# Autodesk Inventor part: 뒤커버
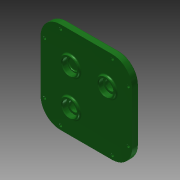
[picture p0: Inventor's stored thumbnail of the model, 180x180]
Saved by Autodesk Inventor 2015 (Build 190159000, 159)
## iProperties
Created: 2016-12
Part Number: 뒤커버
Material: 알루미늄 6061
Document SubType Name: Modeling
Designer: mduedu
Density: 2.71 g/cm^3
Appearance: 매끄러움 - 짙은 산림 녹색
Mass: 485.372 g
Surface Area: 454.562 cm^2
Volume: 179.104 cm^3
Author: mduedu
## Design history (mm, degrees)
sketch "스케치1"
  geometry: L1 (-46, 42)-(-46, -36); L2 (-16, 72)-(62, 72); L3 (92, 42)-(92, -36); L4 (62, -66)-(-16, -66); A1 r 30 centre (-16, -36) between (-46, -36) and (-16, -66); A2 r 30 centre (62, 42) between (92, 42) and (62, 72); A3 r 30 centre (62, -36) between (62, -66) and (92, -36); A4 r 30 centre (-16, 42) between (-16, 72) and (-46, 42); 1 further point
  constraints: 8 end point, 8 point on circle, 8 tangent, 4 centre point, 3 equal radius, 2 perpendicular, 1 horizontal, 1 vertical
  dimensions: "d80" = 30 radius of A2; "d81" = 138 distance between parallel lines of L4 L2; "d82" = 92 distance from line of L3 point (0, 0); "d114" = 46 distance from line of L1 point (0, 0); "d115" = 72 distance from line of L2 point (0, 0)
extrude "돌출1" new body sketch "스케치1" distance "d3" = 10; taper "d4" = 0 deg
sketch "스케치2"
  geometry: C1 r 14 at (0, 26); 1 further point
  constraints: 1 centre point, 1 vertical alignment
  dimensions: "d5" = 28 diameter of C1; "d6" = 26 distance of C1.centre point (0, 0)
extrude "돌출2" join sketch "스케치2" distance "d7" = 3; taper "d8" = 0 deg
sketch "스케치3"
  geometry: C1 r 14 at (0, -28.87); C2 r 14 at (0, 26) reference; C3 r 14 at (54.87, 26); 1 further point
  constraints: 2 centre point, 1 horizontal alignment, 1 vertical alignment
  dimensions: "d9" = 28 diameter of C1; "d69" = 54.87 distance of C1.centre C2.centre; "d83" = 28 diameter of C3; "d84" = 54.87 distance of C3.centre C2.centre
extrude "돌출3" join sketch "스케치3" distance "d11" = 3; taper "d12" = 0 deg
hole "구멍1" diameter "d15" = 22; stored, may be unused: countersink angle "d19" = 90 deg, drill point angle "d21" = 0 deg; dims "d13" = 10, "d14" = 10, "d16" = 6, "d17" = 4, "d18" = 2, "d20" = 7
hole "구멍2" diameter "d24" = 18; stored, may be unused: countersink angle "d28" = 90 deg, drill point angle "d30" = 0 deg; dims "d22" = 10, "d23" = 10, "d25" = 6, "d26" = 4, "d27" = 2, "d29" = 1
hole "구멍3" diameter "d33" = 22; stored, may be unused: countersink angle "d37" = 90 deg, drill point angle "d39" = 0 deg; dims "d31" = 10, "d32" = 10, "d34" = 6, "d35" = 4, "d36" = 2, "d38" = 7
hole "구멍7" diameter "d87" = 22; stored, may be unused: countersink angle "d91" = 90 deg, drill point angle "d93" = 0 deg; dims "d85" = 10, "d86" = 10, "d88" = 6, "d89" = 4, "d90" = 2, "d92" = 7
sketch "스케치4"
  geometry: C1 r 14 at (0, -28.87) reference; C2 r 18 at (0, -28.87); C3 r 14 at (-54.87, 26) reference; C4 r 18 at (-54.87, 26); 1 further point
  constraints: 2 centre point, 2 coincident
  dimensions: "d40" = 36 diameter of C2; "d94" = 36 diameter of C4
extrude "돌출4" join sketch "스케치4" distance "d41" = 4; taper "d42" = 0 deg
hole "구멍4" diameter "d45" = 22; stored, may be unused: countersink angle "d49" = 90 deg, drill point angle "d51" = 0 deg; dims "d43" = 10, "d44" = 10, "d46" = 6, "d47" = 4, "d48" = 2, "d50" = 7
hole "구멍8" diameter "d97" = 22; stored, may be unused: countersink angle "d101" = 90 deg, drill point angle "d103" = 0 deg; dims "d95" = 10, "d96" = 10, "d98" = 6, "d99" = 4, "d100" = 2, "d102" = 7
hole "구멍5" diameter "d54" = 15; stored, may be unused: countersink angle "d58" = 90 deg, drill point angle "d60" = 0 deg; dims "d52" = 10, "d53" = 10, "d55" = 6, "d56" = 4, "d57" = 2, "d59" = 7
hole "구멍9" diameter "d106" = 15; stored, may be unused: countersink angle "d110" = 90 deg, drill point angle "d112" = 0 deg; dims "d104" = 10, "d105" = 10, "d107" = 6, "d108" = 4, "d109" = 2, "d111" = 7
fillet "모깎기1" dims "d61" = 0.3
fillet "모깎기2" dims "d62" = 2
chamfer "모따기1" distance "d63" = 1; stored, may be unused: second distance "d64" = 2, angle "d65" = 45 deg
fillet "모깎기3" dims "d66" = 2
fillet "모깎기4" dims "d67" = 2
fillet "모깎기5" dims "d68" = 2
sketch "스케치5"
  geometry: L1 (-62, 72)-(16, 72) reference; L2 (-92, -36)-(-92, 42) reference; L3 (16, -66)-(-62, -66) reference; L4 (46, 42)-(46, -36) reference; L5 (16, 66)-(-62, 66); L6 (-86, 42)-(-86, -36); L7 (-62, -60)-(16, -60); L8 (40, -36)-(40, 42); A1 r 30 centre (-62, 42) between (-62, 72) and (-92, 42) reference; A2 r 30 centre (-62, -36) between (-92, -36) and (-62, -66) reference; A3 r 30 centre (16, -36) between (16, -66) and (46, -36) reference; A4 r 30 centre (16, 42) between (46, 42) and (16, 72) reference; A5 r 24 centre (-62, 42) between (-62, 66) and (-86, 42); A6 r 24 centre (-62, -36) between (-86, -36) and (-62, -60); A7 r 24 centre (16, -36) between (16, -60) and (40, -36); A8 r 24 centre (16, 42) between (40, 42) and (16, 66)
  constraints: 8 end point, 8 point on circle, 4 centre point, 7 other
  dimensions: "d113" = 6 distance between parallel lines of L6 L2
sketch "스케치6"
  geometry: L1 (16, 66)-(-62, 66) reference; L2 (40, -36)-(40, 42) reference; L3 (-62, -60)-(16, -60) reference; L4 (-86, 42)-(-86, -36) reference; A1 r 24 centre (16, 42) between (40, 42) and (16, 66) reference; A2 r 24 centre (16, -36) between (16, -60) and (40, -36) reference; A3 r 24 centre (-62, -36) between (-86, -36) and (-62, -60) reference; A4 r 24 centre (-62, 42) between (-62, 66) and (-86, 42) reference; 8 further points
  constraints: 8 coincident
hole "구멍6" sketch "스케치6" at (-62, 66), (-86, 42), (-86, -36), (-62, -60), (16, -60), (40, -36), (40, 42), (16, 66) diameter "d71" = 4.5; stored, may be unused: countersink angle "d75" = 90 deg, drill point angle "d77" = 0 deg; dims "d72" = 6, "d73" = 8, "d74" = 4.6, "d76" = 8
node "솔리드1"
